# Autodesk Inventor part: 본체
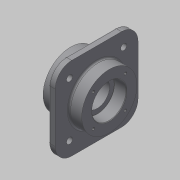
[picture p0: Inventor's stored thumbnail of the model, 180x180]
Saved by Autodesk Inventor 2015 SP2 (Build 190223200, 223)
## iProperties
Created: 2015-07
Part Number: 본체
Material: 일반
Document SubType Name: Modeling
Designer: AMC
Density: 1 g/cm^3
Appearance: 기본값
Author: AMC
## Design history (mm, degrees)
sketch "스케치1"
  geometry: L1 (75, -75)-(-75, -75); L2 (-75, -75)-(-75, 75); L3 (-75, 75)-(75, 75); L4 (75, 75)-(75, -75); L5 (75, -75)-(-75, 75); L6 (-75, -75)-(75, 75); 1 further point
  constraints: 12 end point, 2 midpoint, 2 parallel, 1 horizontal, 1 perpendicular
  dimensions: "d0" = 150 distance of L2.end L3.end; "d1" = 150 distance of L1.end L2.end
extrude "돌출1" new body sketch "스케치1" stored distance "d2" = 12; taper "d3" = 0 deg
fillet "모깎기1" dims "d4" = 30
sketch "스케치2"
  geometry: L1 (45, 75)-(-45, 75) reference; L2 (75, -45)-(75, 45) reference; L3 (-75, 45)-(-75, -45) reference; C1 r 10 at (49, 49); C2 r 10 at (49, -49); C3 r 10 at (-49, -49); C4 r 10 at (-49, 49); 1 further point
  constraints: 4 centre point, 2 horizontal alignment, 1 vertical alignment
  dimensions: "d5" = 20 diameter of C1; "d6" = 20 diameter of C2; "d7" = 20 diameter of C3; "d8" = 20 diameter of C4; "d9" = 98 distance of C2.centre C1.centre; "d10" = 98 distance of C3.centre C2.centre; "d11" = 26 distance from line of L1 C1.centre; "d12" = 26 distance from line of L2 C1.centre; "d13" = 26 distance from line of L3 C4.centre
extrude "돌출2" join sketch "스케치2" distance "d14" = 5; taper "d15" = 0 deg
sketch "스케치3"
  geometry: C1 r 50 at (0, 0); 1 further point
  constraints: 1 centre point, 1 coincident
  dimensions: "d16" = 100 diameter of C1
extrude "돌출3" join sketch "스케치3" distance "d17" = 29; taper "d19" = 0 deg; dims "d18" = 41, "d20" = 0
hole "구멍1" diameter "d23" = 11; stored, may be unused: countersink angle "d27" = 90 deg, drill point angle "d29" = 118 deg; dims "d21" = 10, "d22" = 10, "d24" = 6, "d25" = 4, "d26" = 2, "d28" = 8
hole "구멍2" diameter "d32" = 11; stored, may be unused: countersink angle "d36" = 90 deg, drill point angle "d38" = 118 deg; dims "d30" = 10, "d31" = 10, "d33" = 6, "d34" = 4, "d35" = 2, "d37" = 8
hole "구멍3" diameter "d41" = 11; stored, may be unused: countersink angle "d45" = 90 deg, drill point angle "d47" = 118 deg; dims "d39" = 10, "d40" = 10, "d42" = 6, "d43" = 4, "d44" = 2, "d46" = 8
hole "구멍4" diameter "d50" = 11; stored, may be unused: countersink angle "d54" = 90 deg, drill point angle "d56" = 118 deg; dims "d48" = 10, "d49" = 10, "d51" = 6, "d52" = 4, "d53" = 2, "d55" = 8
hole "구멍5" diameter "d59" = 45; stored, may be unused: countersink angle "d63" = 90 deg, drill point angle "d65" = 118 deg; dims "d57" = 10, "d58" = 10, "d60" = 6, "d61" = 62, "d62" = 22, "d64" = 8
hole "구멍6" diameter "d68" = 62; stored, may be unused: countersink angle "d72" = 90 deg, drill point angle "d74" = 0 deg; dims "d66" = 10, "d67" = 10, "d69" = 6, "d70" = 62, "d71" = 22, "d73" = 22
sketch "스케치4"
  geometry: 2 further points
  constraints: 1 horizontal alignment, 1 other
  dimensions: "d75" = 65 distance of point (0, 0) point (65, 0)
feature "엠보싱1" sketch "스케치4" dims "d0" = 150, "d1" = 150, "d76" = 1, "d77" = 0
sketch "스케치5"
  geometry: L1 (0, 0)-(0, -41); L2 (0, 0)-(28.991, -28.991); A1 r 41 centre (0, 0) between (0, -41) and (28.991, -28.991); 2 further points
  constraints: 4 end point, 2 coincident, 2 point on circle, 1 centre point, 1 vertical
  dimensions: "d78" = 82 diameter of A1; "d79" = 45 deg angle of L1 L2
hole "구멍7" sketch "스케치5" at (28.991, -28.991) diameter "d80" = 4.917; stored, may be unused: countersink angle "d84" = 90 deg, drill point angle "d86" = 118 deg; dims "d81" = 10, "d82" = 62, "d83" = 22, "d85" = 13
sketch "스케치6"
  geometry: L1 (0, 0)-(0, 41); L2 (0, 0)-(-28.991, 28.991); A1 r 41 centre (0, 0) between (0, 41) and (-28.991, 28.991); 2 further points
  constraints: 4 end point, 2 coincident, 2 point on circle, 1 centre point, 1 vertical
  dimensions: "d90" = 82 diameter of A1; "d91" = 45 deg angle of L1 L2
hole "구멍8" sketch "스케치6" at (-28.991, 28.991) diameter "d92" = 4.917; stored, may be unused: countersink angle "d96" = 90 deg, drill point angle "d98" = 118 deg; dims "d93" = 10, "d94" = 62, "d95" = 22, "d97" = 13
fillet "모깎기2" dims "d102" = 3
fillet "모깎기3" dims "d103" = 3
chamfer "모따기1" distance "d104" = 1; stored, may be unused: second distance "d105" = 2, angle "d106" = 45 deg
fillet "모깎기4" dims "d107" = 0.3
node "솔리드1"
pattern_circular "원형 패턴1" dims angle "d88" = 360 deg
pattern_circular "원형 패턴2" dims angle "d100" = 360 deg
